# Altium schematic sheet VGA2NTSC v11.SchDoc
size B
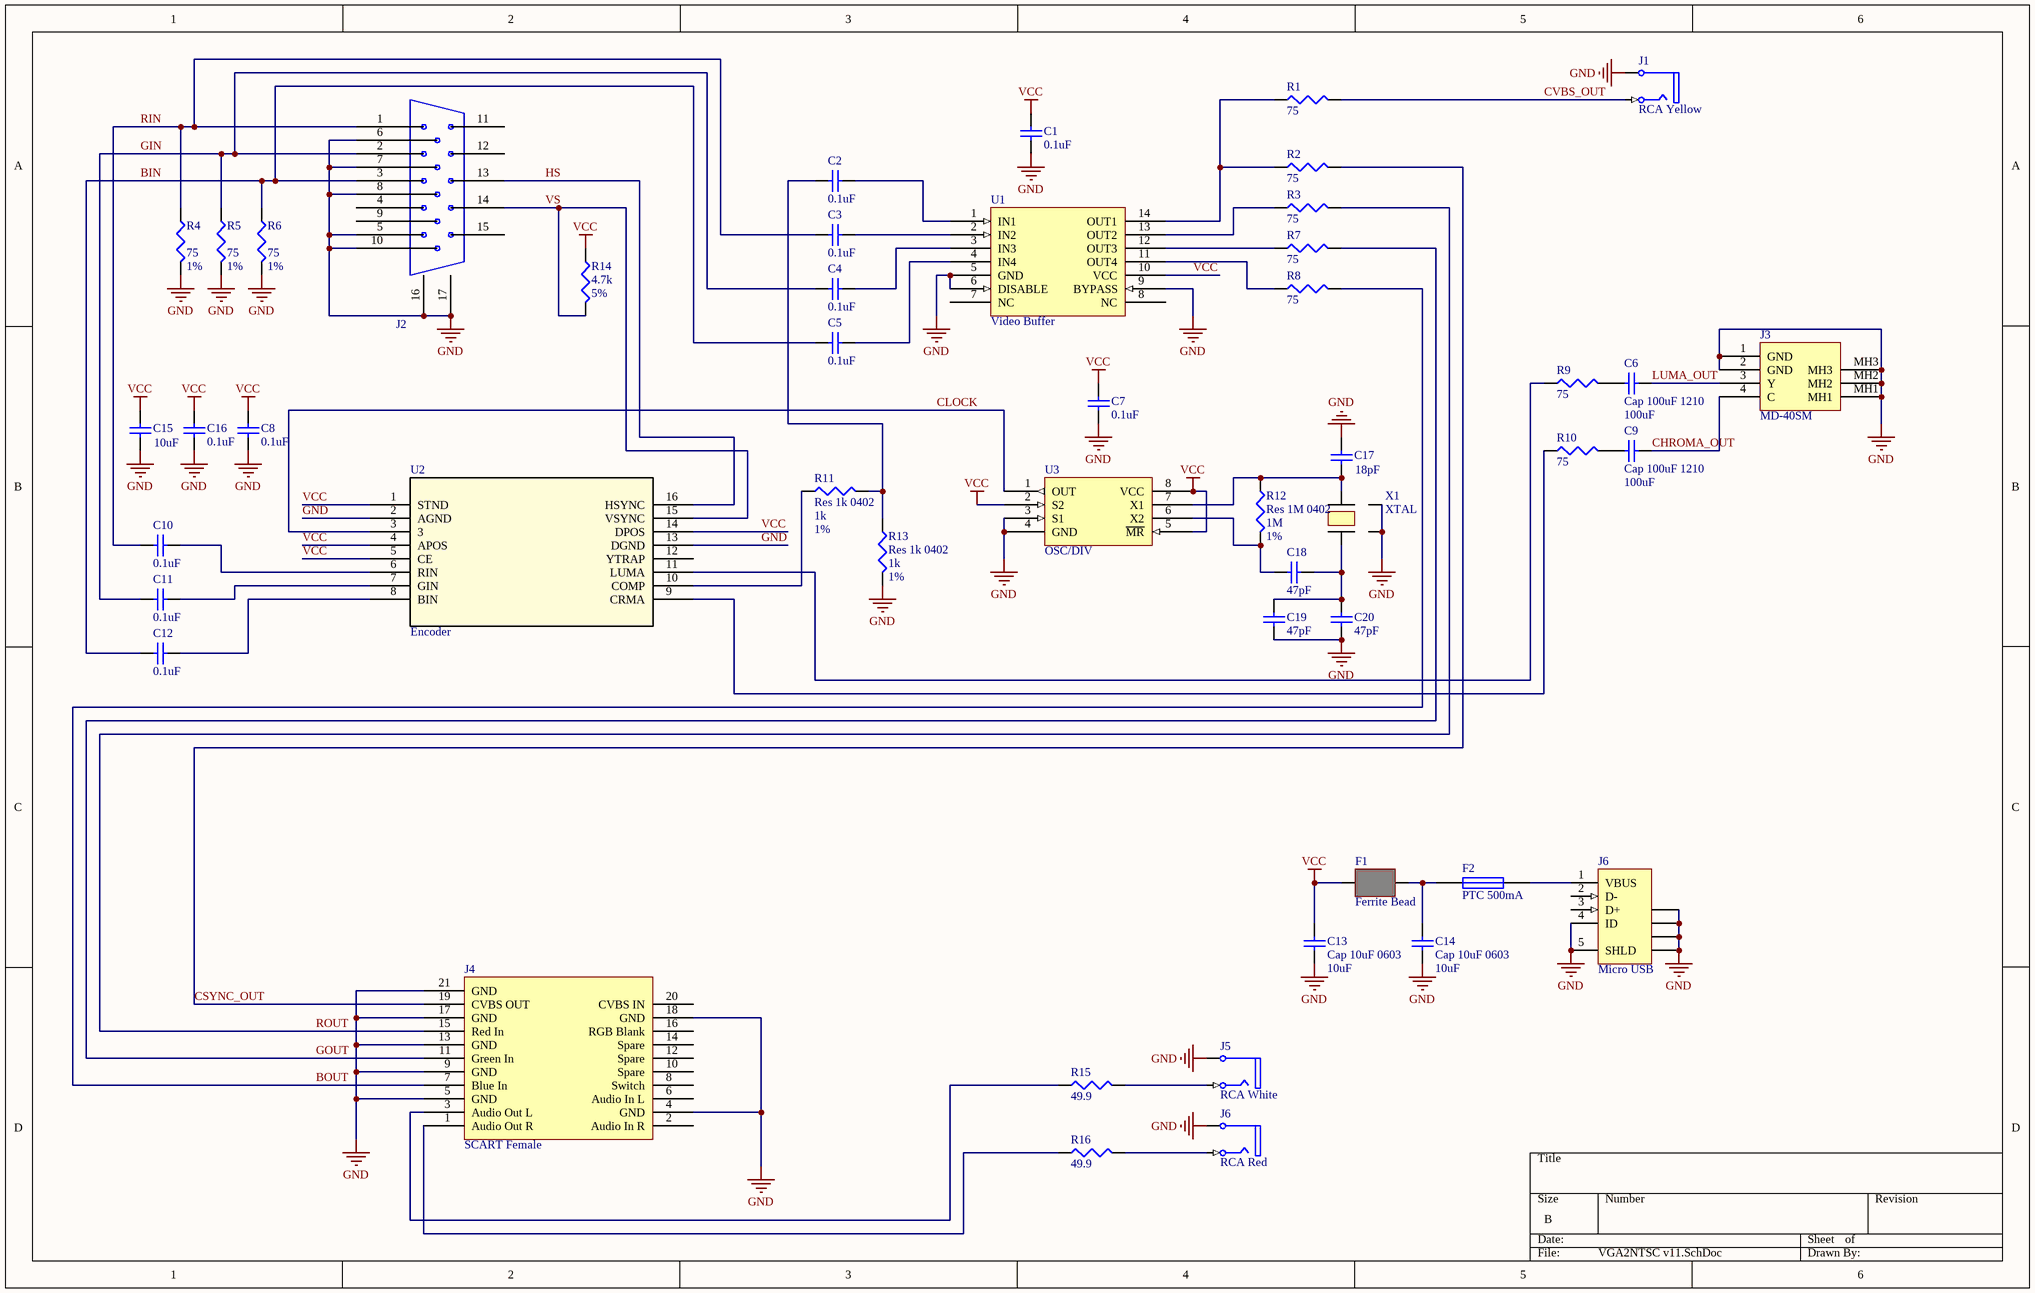
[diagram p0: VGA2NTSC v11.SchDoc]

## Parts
(Parts that share a designator on the sheet are numbered #1, #2 ... from top to bottom, then left to right.)
C1  value 0.1uF  [CAPC1005X05N]  (hidden comment: Cap 0.1uF 0402)
C2  value 0.1uF  [CAPC1005X05N]  (hidden comment: Cap 0.1uF 0402)
C3  value 0.1uF  [CAPC1005X05N]  (hidden comment: Cap 0.1uF 0402)
C4  value 0.1uF  [CAPC1005X05N]  (hidden comment: Cap 0.1uF 0402)
C5  value 0.1uF  [CAPC1005X05N]  (hidden comment: Cap 0.1uF 0402)
C6  Cap 100uF 1210  value 100uF  [CAPC3225X25N]
C7  value 0.1uF  [CAPC1005X05N]  (hidden comment: Cap 0.1uF 0402)
C8  value 0.1uF  [CAPC1005X05N]  (hidden comment: Cap 0.1uF 0402)
C9  Cap 100uF 1210  value 100uF  [CAPC3225X25N]
C10  value 0.1uF  [CAPC1005X05N]  (hidden comment: Cap 0.1uF 0402)
C11  value 0.1uF  [CAPC1005X05N]  (hidden comment: Cap 0.1uF 0402)
C12  value 0.1uF  [CAPC1005X05N]  (hidden comment: Cap 0.1uF 0402)
C13  Cap 10uF 0603  value 10uF  [CAPC1608X09N]
C14  Cap 10uF 0603  value 10uF  [CAPC1608X09N]
C15  value 10uF  [CAPC1608X09N]  (hidden comment: Cap 10uF 0603)
C16  value 0.1uF  [CAPC1005X05N]  (hidden comment: Cap 0.1uF 0402)
C17  value 18pF  [CAPC1005X05N]  (hidden comment: Cap 18pF 0402)
C18  value 47pF  [CAPC1005X05N]  (hidden comment: Cap 47pF 0402)
C19  value 47pF  [CAPC1005X05N]  (hidden comment: Cap 47pF 0402)
C20  value 47pF  [CAPC1005X05N]  (hidden comment: Cap 47pF 0402)
F1  Ferrite Bead  [CAPC1005X05N]
F2  PTC 500mA  [PTC1206]
J1  RCA Yellow  [RCJ-044]
J2  DB-15 VGA  [DB-15 VGA]  (value not drawn)
J3  MD-40SM  [CDIN2.6-3H4A]
J4  SCART Female  [SCART FEMALE]
J5  RCA White  [RCJ-043]
J6#1  Micro USB  [MICROUSB]
J6#2  RCA Red  [RCJ-042]
R1  value 75  [RESC1005X03N]  (hidden comment: Res 75 0402)
R2  value 75  [RESC1005X03N]  (hidden comment: Res 75 0402)
R3  value 75  [RESC1005X03N]  (hidden comment: Res 75 0402)
R4  value 75  Tolerance: 1%  [RESC1005X03N]  (hidden comment: Res 75 0402)
R5  value 75  Tolerance: 1%  [RESC1005X03N]  (hidden comment: Res 75 0402)
R6  value 75  Tolerance: 1%  [RESC1005X03N]  (hidden comment: Res 75 0402)
R7  value 75  [RESC1005X03N]  (hidden comment: Res 75 0402)
R8  value 75  [RESC1005X03N]  (hidden comment: Res 75 0402)
R9  value 75  [RESC1005X03N]  (hidden comment: Res 75 0402)
R10  value 75  [RESC1005X03N]  (hidden comment: Res 75 0402)
R11  Res 1k 0402  value 1k  Tolerance: 1%  [RESC1005X03N]
R12  Res 1M 0402  value 1M  Tolerance: 1%  [RESC1005X03N]
R13  Res 1k 0402  value 1k  Tolerance: 1%  [RESC1005X03N]
R14  value 4.7k  Tolerance: 5%  [RESC1005X03N]  (hidden comment: Res 4.7k)
R15  value 49.9  [RESC1005X03N]  (hidden comment: Res 49.9 0402)
R16  value 49.9  [RESC1005X03N]  (hidden comment: Res 49.9 0402)
U1  Video Buffer  [TSOP65P640X120-14N]
U2  Encoder  [SOIC127P1030X237-16N]
U3  OSC/DIV  [SOIC127P600X175_HS-8N]
X1  XTAL  [ABM8-28.63636MHZ-B2-T]

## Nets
GND: C1.1 C7.1 C8.1 C13.2 C14.2 C15.2 C16.1 C17.1 C19.1 C20.1 J1.1A(Ground) J2.5 J2.6 J2.7 J2.8 J2.10 J2.16 J2.17 J3.1(GND) J3.2(GND) J3.MH1 J3.MH2 J3.MH3 J4.4(GND) J4.5(GND) J4.9(GND) J4.13(GND) J4.17(GND) J4.18(GND) J4.21(GND) J5.1A(Ground) J6#1.4(ID) J6#1.5(SHLD) J6#1.6(SHLD) J6#1.7(SHLD) J6#1.8(SHLD) J6#1.9(SHLD) J6#2.1A(Ground) R4.2 R5.2 R6.2 R13.2 U1.5(GND) U1.6(DISABLE) U1.9(BYPASS) U2.2(AGND) U2.13(DGND) U3.3(S1) U3.4(GND) X1.2 X1.4
VCC: C1.2 C7.2 C8.2 C13.1 C15.1 C16.2 F1.1 R14.1 U1.10(VCC) U2.1(STND) U2.4(APOS) U2.5(CE) U2.14(DPOS) U3.2(S2) U3.5(~{MR}) U3.8(VCC)
BIN: C5.1 C12.1 J2.3 R6.1
BOUT: J4.7(Blue_In) R8.2
CHROMA_OUT: C9.2 J3.4(C)
CLOCK: U2.3 U3.1(OUT)
CSYNC_OUT: J4.19(CVBS_OUT) R2.2
CVBS_OUT: J1.2B(Signal) R1.2
GIN: C4.1 C11.1 J2.2 R5.1
GOUT: J4.11(Green_In) R7.2
HS: J2.13 U2.16(HSYNC)
LUMA_OUT: C6.2 J3.3(Y)
RIN: C3.1 C10.1 J2.1 R4.1
ROUT: J4.15(Red_In) R3.2
VS: J2.14 R14.2 U2.15(VSYNC)
NetC2_1: C2.1 R11.2 R13.1
NetC2_2: C2.2 U1.1(IN1)
NetC3_2: C3.2 U1.2(IN2)
NetC4_2: C4.2 U1.3(IN3)
NetC5_2: C5.2 U1.4(IN4)
NetC6_1: C6.1 R9.2
NetC9_1: C9.1 R10.2
NetC10_2: C10.2 U2.6(RIN)
NetC11_2: C11.2 U2.7(GIN)
NetC12_2: C12.2 U2.8(BIN)
NetC14_1: C14.1 F1.2 F2.1
NetC17_2: C17.2 R12.1 U3.7(X1) X1.3
NetC18_1: C18.1 R12.2 U3.6(X2)
NetC18_2: C18.2 C19.2 C20.2 X1.1
NetF2_2: F2.2 J6#1.1(VBUS)
NetJ4_1: J4.1(Audio_Out_R) R16.1
NetJ4_3: J4.3(Audio_Out_L) R15.1
NetJ5_2B: J5.2B(Signal) R15.2
NetJ6#2_2B: J6#2.2B(Signal) R16.2
NetR1_1: R1.1 R2.1 U1.14(OUT1)
NetR3_1: R3.1 U1.13(OUT2)
NetR7_1: R7.1 U1.12(OUT3)
NetR8_1: R8.1 U1.11(OUT4)
NetR9_1: R9.1 U2.11(LUMA)
NetR10_1: R10.1 U2.9(CRMA)
NetR11_1: R11.1 U2.10(COMP)

Not connected (* = marked no-connect by the designer): J2 4 9 11 12 15; J4 2(Audio_In_R) 6(Audio_In_L) 8(Switch) 10(Spare) 12(Spare) 14(Spare) 16(RGB_Blank) 20(CVBS_IN); J6#1 2(D-) 3(D+); U1 7(NC) 8(NC); U2 12(YTRAP)

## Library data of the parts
C1-C5 C7 C8 C10-C12 C16 = Cap 0.1uF 0402: Capacitor; ManufacturerPartNumber: CL05B104JO5NNNC; Dielectric: X7R; Voltage: 16V
C6 C9 = Cap 100uF 1210: Capacitor; ManufacturerPartNumber: GRM32ER61A107ME20L; Voltage: 10V; Dielectric: X5R
C13-C15 = Cap 10uF 0603: Capacitor; ManufacturerPartNumber: GRM188R61A106KE69J; Voltage: 10V; Dielectric: X5R
C17 = Cap 18pF 0402: Capacitor; ManufacturerPartNumber: CL05C180JB5NNNC; Dielectric: C0G; Voltage: 50V
C18-C20 = Cap 47pF: Capacitor; ManufacturerPartNumber: C0402C470K5GACTU; Dielectric: C0G; Voltage: 50V
F1 = BLM15PX221SN1D: Ferrite Bead 220 Ohm 100Mhz 100mOhm DC
F2 = PTC Fuse: PTC Fuse 500mA; ManufacturerPartNumber: 0ZCJ0050AF2E
J1 = RCJ-044: RCA Jack Yellow
J2 = DB-15 VGA: ManufacturerPartNumber: ICD15S13E4GX00LF
J3 = MD-40SM: DIN-4 S-Video Jack
J4 = SCART
J5 = RCJ-043: RCA Jack White
J6#1 = MICROUSB: ManufacturerPartNumber: 10118194-0001LF
J6#2 = RCJ-042: RCA Jack Red
R1-R3 R7-R10 = Res 75 0402: Resistor 75 0402; ManufacturerPartNumber: RC0402FR-0775RL; Tolerance: 1%
R4-R6 = Res 75 0402: Resistor 75 0402; ManufacturerPartNumber: RC0402FR-0775RL
R11 R13 = Res 1k 0402: Resistor 1k 0402; ManufacturerPartNumber: RC1005F102CS
R12 = Res 1M 0402: Resistor 1M 0402; ManufacturerPartNumber: RC1005F105CS
R14 = Res 4.7k 0402: Resistor 4.7k 0402; ManufacturerPartNumber: RCS1005J472CS
R15 R16 = Res 49.9 0402: Resistor 49.9 0402; ManufacturerPartNumber: RC1005F49R9CS; Tolerance: 1%
U1 = TSH7373: ManufacturerPartNumber: THS7373IPWR
U2 = AD725ARZ: RGB to Video Encoder
U3 = 74HC6323AD: Counter + Oscillator; MFG: 74HC6323AD,112
X1 = ABM8-28.63636MHZ-B2-T: CRYSTAL 28.63636MHZ 18PF SMD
